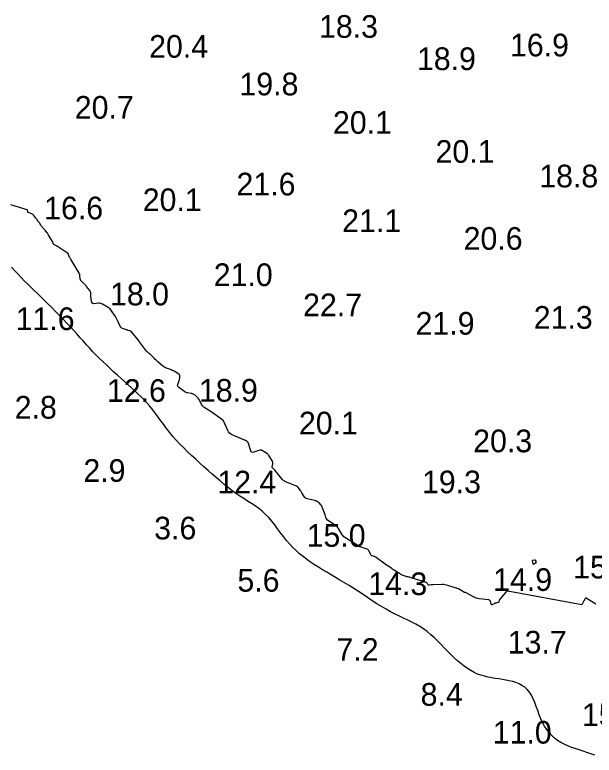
# Model space of a CAD drawing. Extents: x 3040093 to 3056816, y 408076 to 509144.
# Drawn here: x 3044162.7 to 3044290.6, y 435590.3 to 435753.7 of the extents above; entities that cross this region are included whole.
import ezdxf

# ---------------------------------------------------------------- set-up
doc = ezdxf.new("R2010")
doc.units = 0
for name, color, linetype in [('V-CHAN-CONT-EL12-1112', 7, 'Continuous'), ('V-CHAN-CONT-EL15', 7, 'Continuous'), ('V-TOPO-SOUN-0810', 7, 'Continuous')]:
    doc.layers.add(name, color=color, linetype=linetype)

msp = doc.modelspace()

# ---------------------------------------------------------------- linework, layer by layer
at = {"layer": 'V-CHAN-CONT-EL12-1112'}
msp.add_lwpolyline([(3044290.76, 435590.32), (3044289.9, 435590.65), (3044289.03, 435590.95), (3044288.16, 435591.23), (3044287.29, 435591.49), (3044286.43, 435591.77), (3044285.59, 435592.05), (3044284.77, 435592.37), (3044283.99, 435592.73), (3044283.24, 435593.13), (3044282.54, 435593.6), (3044281.88, 435594.11), (3044281.26, 435594.68), (3044280.68, 435595.3), (3044280.15, 435595.99), (3044279.67, 435596.72), (3044279.24, 435597.52), (3044278.85, 435598.37), (3044278.5, 435599.25), (3044278.16, 435600.16), (3044277.84, 435601.06), (3044277.51, 435601.93), (3044277.15, 435602.77), (3044276.77, 435603.54), (3044276.33, 435604.23), (3044275.83, 435604.81), (3044275.28, 435605.31), (3044274.68, 435605.72), (3044274.03, 435606.06), (3044273.34, 435606.34), (3044272.63, 435606.56), (3044271.89, 435606.74), (3044271.13, 435606.9), (3044270.36, 435607.03), (3044269.58, 435607.15), (3044268.79, 435607.27), (3044268.01, 435607.4), (3044267.22, 435607.55), (3044266.44, 435607.73), (3044265.66, 435607.96), (3044264.89, 435608.24), (3044264.13, 435608.59), (3044263.38, 435608.99), (3044262.64, 435609.45), (3044261.91, 435609.96), (3044261.19, 435610.53), (3044260.46, 435611.14), (3044259.74, 435611.79), (3044259.02, 435612.48), (3044258.3, 435613.21), (3044257.57, 435613.96), (3044256.84, 435614.72), (3044256.1, 435615.48), (3044255.34, 435616.22), (3044254.57, 435616.92), (3044253.78, 435617.59), (3044252.97, 435618.2), (3044252.13, 435618.75), (3044251.27, 435619.24), (3044250.39, 435619.7), (3044249.49, 435620.13), (3044248.56, 435620.56), (3044247.62, 435621), (3044246.66, 435621.46), (3044245.69, 435621.97), (3044244.69, 435622.52), (3044243.69, 435623.12), (3044242.67, 435623.76), (3044241.65, 435624.42), (3044240.62, 435625.1), (3044239.59, 435625.78), (3044238.56, 435626.46), (3044237.54, 435627.12), (3044236.52, 435627.76), (3044235.51, 435628.37), (3044234.51, 435628.97), (3044233.53, 435629.55), (3044232.56, 435630.12), (3044231.6, 435630.68), (3044230.67, 435631.24), (3044229.76, 435631.8), (3044228.87, 435632.37), (3044228.01, 435632.95), (3044227.17, 435633.54), (3044226.35, 435634.15), (3044225.57, 435634.79), (3044224.81, 435635.47), (3044224.07, 435636.18), (3044223.37, 435636.94), (3044222.69, 435637.74), (3044222.03, 435638.57), (3044221.39, 435639.43), (3044220.75, 435640.29), (3044220.1, 435641.14), (3044219.45, 435641.96), (3044218.77, 435642.75), (3044218.07, 435643.48), (3044217.33, 435644.15), (3044216.57, 435644.76), (3044215.77, 435645.34), (3044214.96, 435645.89), (3044214.12, 435646.42), (3044213.27, 435646.96), (3044212.41, 435647.52), (3044211.54, 435648.1), (3044210.67, 435648.73), (3044209.8, 435649.4), (3044208.92, 435650.1), (3044208.04, 435650.84), (3044207.16, 435651.6), (3044206.27, 435652.38), (3044205.38, 435653.18), (3044204.48, 435653.99), (3044203.57, 435654.8), (3044202.67, 435655.63), (3044201.77, 435656.46), (3044200.88, 435657.29), (3044200.02, 435658.13), (3044199.18, 435658.98), (3044198.38, 435659.83), (3044197.63, 435660.69), (3044196.92, 435661.55), (3044196.24, 435662.41), (3044195.6, 435663.27), (3044194.99, 435664.11), (3044194.38, 435664.95), (3044193.79, 435665.76), (3044193.19, 435666.55), (3044192.57, 435667.32), (3044191.94, 435668.05), (3044191.29, 435668.75), (3044190.61, 435669.43), (3044189.92, 435670.1), (3044189.21, 435670.77), (3044188.48, 435671.43), (3044187.73, 435672.09), (3044186.97, 435672.77), (3044186.19, 435673.46), (3044185.4, 435674.17), (3044184.6, 435674.89), (3044183.8, 435675.63), (3044183.01, 435676.37), (3044182.22, 435677.12), (3044181.45, 435677.87), (3044180.7, 435678.62), (3044179.98, 435679.38), (3044179.27, 435680.14), (3044178.57, 435680.9), (3044177.88, 435681.67), (3044177.18, 435682.44), (3044176.47, 435683.23), (3044175.74, 435684.04), (3044174.99, 435684.86), (3044174.2, 435685.7), (3044173.38, 435686.55), (3044172.55, 435687.41), (3044171.71, 435688.27), (3044170.87, 435689.11), (3044170.03, 435689.94), (3044169.21, 435690.75), (3044168.42, 435691.52), (3044167.66, 435692.26), (3044166.93, 435692.97), (3044166.21, 435693.66), (3044165.52, 435694.34), (3044164.83, 435695.03), (3044164.14, 435695.73), (3044163.44, 435696.45), (3044162.73, 435697.21), (3044162.01, 435698.01)], dxfattribs=at)
at = {"layer": 'V-CHAN-CONT-EL15'}
for points in [[(3044287.86, 435623.51), (3044271.91, 435626.42), (3044271.7, 435626.49), (3044271.5, 435626.49), (3044271.32, 435626.42), (3044271.15, 435626.27), (3044269.78, 435624.73), (3044269.73, 435624.67), (3044269.69, 435624.61), (3044269.66, 435624.54), (3044269.64, 435624.47), (3044269.56, 435624.18), (3044269.54, 435624.12), (3044269.5, 435624.06), (3044269.45, 435624.03), (3044269.38, 435624), (3044268.9, 435623.89), (3044268.8, 435623.86), (3044268.71, 435623.83), (3044268.61, 435623.79), (3044268.52, 435623.74), (3044268.15, 435623.55), (3044268.07, 435623.52), (3044268, 435623.53), (3044267.95, 435623.57), (3044267.91, 435623.65), (3044267.73, 435624.28), (3044267.68, 435624.41), (3044267.6, 435624.5), (3044267.49, 435624.56), (3044267.36, 435624.59), (3044265.25, 435624.86), (3044264.91, 435624.92), (3044264.59, 435625), (3044264.27, 435625.12), (3044263.96, 435625.27), (3044262.18, 435626.22), (3044262.17, 435626.23), (3044262.15, 435626.24), (3044262.14, 435626.24), (3044262.12, 435626.24), (3044262.06, 435626.23), (3044262.04, 435626.23), (3044262.03, 435626.23), (3044262.01, 435626.23), (3044262, 435626.24), (3044261.07, 435626.79), (3044261.03, 435626.82), (3044260.98, 435626.84), (3044260.94, 435626.86), (3044260.9, 435626.89), (3044260.66, 435627.02), (3044260.65, 435627.02), (3044260.64, 435627.02), (3044260.63, 435627.03), (3044260.62, 435627.03), (3044260.33, 435627.14), (3044260.28, 435627.16), (3044260.23, 435627.18), (3044260.18, 435627.19), (3044260.13, 435627.21), (3044258.33, 435627.79), (3044258.01, 435627.87), (3044257.69, 435627.94), (3044257.36, 435627.97), (3044257.03, 435627.98), (3044255.11, 435627.94), (3044255, 435627.94), (3044254.89, 435627.93), (3044254.78, 435627.93), (3044254.67, 435627.91), (3044254.18, 435627.86), (3044254.1, 435627.86), (3044254.04, 435627.88), (3044253.98, 435627.92), (3044253.93, 435627.98), (3044253.75, 435628.26), (3044253.71, 435628.33), (3044253.65, 435628.38), (3044253.58, 435628.43), (3044253.51, 435628.46), (3044250.01, 435629.56), (3044249.94, 435629.59), (3044249.87, 435629.61), (3044249.8, 435629.62), (3044249.72, 435629.64), (3044249.43, 435629.69), (3044249.36, 435629.71), (3044249.28, 435629.72), (3044249.21, 435629.75), (3044249.14, 435629.77), (3044248.26, 435630.09), (3044248.09, 435630.16), (3044247.93, 435630.23), (3044247.77, 435630.32), (3044247.62, 435630.41), (3044246.35, 435631.24), (3044246.22, 435631.32), (3044246.09, 435631.41), (3044245.97, 435631.49), (3044245.84, 435631.58), (3044245.19, 435632.02), (3044245.14, 435632.06), (3044245.08, 435632.1), (3044245.02, 435632.13), (3044244.96, 435632.17), (3044244.72, 435632.31), (3044244.67, 435632.35), (3044244.61, 435632.39), (3044244.55, 435632.42), (3044244.5, 435632.47), (3044242.49, 435633.95), (3044242.39, 435634.03), (3044242.28, 435634.09), (3044242.17, 435634.14), (3044242.05, 435634.19), (3044241.57, 435634.35), (3044241.46, 435634.4), (3044241.37, 435634.47), (3044241.29, 435634.56), (3044241.23, 435634.67), (3044240.94, 435635.38), (3044240.86, 435635.53), (3044240.76, 435635.65), (3044240.63, 435635.74), (3044240.48, 435635.81), (3044239.19, 435636.24), (3044239.16, 435636.25), (3044239.12, 435636.26), (3044239.08, 435636.27), (3044239.05, 435636.28), (3044238.83, 435636.33), (3044238.83, 435636.33), (3044238.83, 435636.34), (3044238.82, 435636.34), (3044238.81, 435636.35), (3044235.57, 435638.4), (3044235.38, 435638.54), (3044235.2, 435638.7), (3044235.05, 435638.88), (3044234.92, 435639.07), (3044234.25, 435640.21), (3044234.22, 435640.27), (3044234.18, 435640.33), (3044234.14, 435640.39), (3044234.1, 435640.45), (3044233.94, 435640.68), (3044233.9, 435640.74), (3044233.86, 435640.79), (3044233.8, 435640.84), (3044233.75, 435640.88), (3044231.87, 435642.09), (3044231.82, 435642.13), (3044231.77, 435642.18), (3044231.72, 435642.23), (3044231.68, 435642.28), (3044231.54, 435642.51), (3044231.51, 435642.57), (3044231.47, 435642.63), (3044231.45, 435642.7), (3044231.42, 435642.76), (3044231.22, 435643.34), (3044231.18, 435643.46), (3044231.14, 435643.57), (3044231.1, 435643.69), (3044231.06, 435643.81), (3044230.52, 435645.24), (3044230.48, 435645.34), (3044230.43, 435645.43), (3044230.37, 435645.52), (3044230.3, 435645.6), (3044229.98, 435645.92), (3044229.91, 435645.99), (3044229.84, 435646.05), (3044229.76, 435646.11), (3044229.68, 435646.16), (3044229.34, 435646.36), (3044229.25, 435646.4), (3044229.16, 435646.44), (3044229.07, 435646.47), (3044228.97, 435646.5), (3044227.25, 435646.91), (3044227.05, 435646.98), (3044226.88, 435647.08), (3044226.73, 435647.22), (3044226.61, 435647.39), (3044226.12, 435648.26), (3044226.04, 435648.39), (3044225.96, 435648.52), (3044225.88, 435648.64), (3044225.79, 435648.77), (3044225.28, 435649.42), (3044225.26, 435649.45), (3044225.23, 435649.48), (3044225.2, 435649.51), (3044225.17, 435649.54), (3044225.05, 435649.64), (3044225.01, 435649.67), (3044224.98, 435649.69), (3044224.95, 435649.71), (3044224.91, 435649.72), (3044222.34, 435650.72), (3044222.33, 435650.73), (3044222.32, 435650.74), (3044222.31, 435650.75), (3044222.3, 435650.76), (3044222.27, 435650.81), (3044222.26, 435650.82), (3044222.26, 435650.83), (3044222.25, 435650.84), (3044222.23, 435650.85), (3044221.93, 435651.04), (3044221.87, 435651.08), (3044221.82, 435651.12), (3044221.78, 435651.16), (3044221.73, 435651.21), (3044220.1, 435653.24), (3044220.04, 435653.3), (3044219.99, 435653.36), (3044219.93, 435653.42), (3044219.88, 435653.48), (3044219.64, 435653.71), (3044219.59, 435653.77), (3044219.56, 435653.83), (3044219.55, 435653.9), (3044219.55, 435653.98), (3044219.68, 435654.66), (3044219.69, 435654.8), (3044219.68, 435654.94), (3044219.64, 435655.06), (3044219.58, 435655.19), (3044218.84, 435656.45), (3044218.76, 435656.57), (3044218.67, 435656.68), (3044218.56, 435656.77), (3044218.45, 435656.86), (3044217.88, 435657.24), (3044217.79, 435657.29), (3044217.71, 435657.34), (3044217.62, 435657.39), (3044217.54, 435657.43), (3044217.18, 435657.61), (3044217.1, 435657.65), (3044217.01, 435657.66), (3044216.91, 435657.66), (3044216.82, 435657.64), (3044215.49, 435657.19), (3044215.26, 435657.14), (3044215.07, 435657.19), (3044214.92, 435657.31), (3044214.82, 435657.52), (3044214.23, 435659.3), (3044214.21, 435659.35), (3044214.18, 435659.4), (3044214.15, 435659.44), (3044214.11, 435659.48), (3044213.88, 435659.68), (3044213.86, 435659.69), (3044213.85, 435659.7), (3044213.83, 435659.71), (3044213.81, 435659.72), (3044213.73, 435659.74), (3044213.71, 435659.74), (3044213.69, 435659.75), (3044213.67, 435659.75), (3044213.65, 435659.76), (3044213.45, 435659.84), (3044213.41, 435659.86), (3044213.38, 435659.88), (3044213.34, 435659.89), (3044213.3, 435659.91), (3044210.74, 435661), (3044210.41, 435661.18), (3044210.13, 435661.4), (3044209.9, 435661.68), (3044209.72, 435662), (3044208.8, 435664.08), (3044208.8, 435664.1), (3044208.79, 435664.11), (3044208.79, 435664.12), (3044208.78, 435664.13), (3044208.76, 435664.17), (3044208.75, 435664.18), (3044208.74, 435664.19), (3044208.74, 435664.2), (3044208.73, 435664.2), (3044208.71, 435664.24), (3044208.7, 435664.25), (3044208.7, 435664.25), (3044208.69, 435664.26), (3044208.68, 435664.26), (3044208.65, 435664.26), (3044208.64, 435664.26), (3044208.63, 435664.26), (3044208.63, 435664.26), (3044208.62, 435664.27), (3044206.3, 435665.94), (3044206.1, 435666.07), (3044205.9, 435666.21), (3044205.69, 435666.34), (3044205.49, 435666.47), (3044204.66, 435666.96), (3044204.46, 435667.1), (3044204.29, 435667.26), (3044204.14, 435667.44), (3044204.01, 435667.64), (3044203.36, 435668.87), (3044203.31, 435668.96), (3044203.25, 435669.05), (3044203.19, 435669.13), (3044203.12, 435669.21), (3044202.83, 435669.51), (3044202.76, 435669.58), (3044202.68, 435669.65), (3044202.6, 435669.71), (3044202.51, 435669.76), (3044202.09, 435669.99), (3044201.99, 435670.04), (3044201.88, 435670.08), (3044201.78, 435670.12), (3044201.67, 435670.14), (3044200.87, 435670.27), (3044200.7, 435670.3), (3044200.55, 435670.36), (3044200.4, 435670.43), (3044200.25, 435670.52), (3044198.86, 435671.54), (3044198.72, 435671.67), (3044198.65, 435671.81), (3044198.64, 435671.97), (3044198.68, 435672.15), (3044199.02, 435673.02), (3044199.06, 435673.14), (3044199.1, 435673.26), (3044199.12, 435673.39), (3044199.13, 435673.51), (3044199.16, 435674.02), (3044199.16, 435674.14), (3044199.12, 435674.24), (3044199.06, 435674.33), (3044198.96, 435674.4), (3044197.89, 435675.05), (3044197.69, 435675.16), (3044197.49, 435675.26), (3044197.28, 435675.35), (3044197.07, 435675.44), (3044196.21, 435675.75), (3044196, 435675.83), (3044195.8, 435675.94), (3044195.61, 435676.06), (3044195.43, 435676.2), (3044194.3, 435677.16), (3044194.1, 435677.33), (3044193.92, 435677.5), (3044193.73, 435677.68), (3044193.55, 435677.85), (3044192.6, 435678.82), (3044192.54, 435678.88), (3044192.48, 435678.93), (3044192.41, 435678.99), (3044192.35, 435679.04), (3044192.07, 435679.25), (3044192.01, 435679.3), (3044191.94, 435679.36), (3044191.89, 435679.42), (3044191.83, 435679.49), (3044190.04, 435681.83), (3044190.04, 435681.84), (3044190.04, 435681.84), (3044190.04, 435681.84), (3044190.04, 435681.85), (3044190.04, 435681.86), (3044190.04, 435681.86), (3044190.04, 435681.87), (3044190.04, 435681.87), (3044190.03, 435681.87), (3044190.02, 435681.88), (3044190.01, 435681.88), (3044190.01, 435681.88), (3044190.01, 435681.89), (3044190, 435681.89), (3044188.46, 435683.78), (3044188.4, 435683.84), (3044188.32, 435683.9), (3044188.24, 435683.94), (3044188.15, 435683.97), (3044187.78, 435684.07), (3044187.69, 435684.09), (3044187.6, 435684.12), (3044187.51, 435684.14), (3044187.42, 435684.18), (3044186.49, 435684.5), (3044186.32, 435684.58), (3044186.18, 435684.69), (3044186.06, 435684.82), (3044185.97, 435684.99), (3044185.55, 435685.96), (3044185.5, 435686.07), (3044185.45, 435686.18), (3044185.4, 435686.29), (3044185.34, 435686.39), (3044185.12, 435686.82), (3044185.07, 435686.93), (3044185.01, 435687.03), (3044184.95, 435687.13), (3044184.88, 435687.23), (3044184.1, 435688.41), (3044183.93, 435688.63), (3044183.75, 435688.82), (3044183.54, 435689), (3044183.32, 435689.15), (3044182.09, 435689.87), (3044181.9, 435689.97), (3044181.7, 435690.03), (3044181.5, 435690.06), (3044181.28, 435690.06), (3044180.13, 435689.97), (3044180.06, 435689.97), (3044180, 435689.99), (3044179.94, 435690.03), (3044179.9, 435690.08), (3044179.73, 435690.34), (3044179.69, 435690.4), (3044179.66, 435690.47), (3044179.64, 435690.54), (3044179.63, 435690.61), (3044179.58, 435691), (3044179.56, 435691.09), (3044179.56, 435691.18), (3044179.55, 435691.27), (3044179.54, 435691.36), (3044179.51, 435692.24), (3044179.49, 435692.41), (3044179.44, 435692.57), (3044179.37, 435692.73), (3044179.28, 435692.87), (3044178.59, 435693.77), (3044178.47, 435693.92), (3044178.34, 435694.07), (3044178.21, 435694.21), (3044178.07, 435694.34), (3044177.42, 435694.94), (3044177.33, 435695.04), (3044177.26, 435695.15), (3044177.21, 435695.28), (3044177.18, 435695.41), (3044177.09, 435696.22), (3044177.08, 435696.24), (3044177.08, 435696.26), (3044177.08, 435696.28), (3044177.08, 435696.3), (3044177.07, 435696.38), (3044177.07, 435696.4), (3044177.07, 435696.42), (3044177.06, 435696.44), (3044177.05, 435696.46), (3044176.99, 435696.58), (3044176.97, 435696.61), (3044176.96, 435696.63), (3044176.95, 435696.66), (3044176.93, 435696.68), (3044175.16, 435699.66), (3044175.12, 435699.72), (3044175.09, 435699.78), (3044175.05, 435699.84), (3044175.01, 435699.9), (3044174.85, 435700.13), (3044174.81, 435700.19), (3044174.78, 435700.25), (3044174.75, 435700.32), (3044174.73, 435700.38), (3044174.6, 435700.84), (3044174.56, 435700.93), (3044174.51, 435701.01), (3044174.44, 435701.08), (3044174.36, 435701.14), (3044172.15, 435702.57), (3044172.06, 435702.63), (3044171.97, 435702.68), (3044171.88, 435702.73), (3044171.79, 435702.78), (3044171.37, 435703), (3044171.31, 435703.03), (3044171.27, 435703.08), (3044171.24, 435703.13), (3044171.22, 435703.19), (3044171.17, 435703.44), (3044171.16, 435703.51), (3044171.14, 435703.57), (3044171.11, 435703.63), (3044171.08, 435703.68), (3044170.07, 435705.27), (3044169.99, 435705.39), (3044169.92, 435705.5), (3044169.85, 435705.6), (3044169.77, 435705.71), (3044169.43, 435706.18), (3044169.36, 435706.26), (3044169.3, 435706.35), (3044169.23, 435706.43), (3044169.15, 435706.51), (3044168.85, 435706.82), (3044168.78, 435706.9), (3044168.71, 435706.98), (3044168.64, 435707.07), (3044168.58, 435707.15), (3044168.15, 435707.79), (3044168.09, 435707.88), (3044168.03, 435707.97), (3044167.96, 435708.06), (3044167.9, 435708.15), (3044167.65, 435708.51), (3044167.58, 435708.6), (3044167.52, 435708.69), (3044167.45, 435708.78), (3044167.38, 435708.87), (3044166.94, 435709.41), (3044166.84, 435709.52), (3044166.73, 435709.62), (3044166.6, 435709.7), (3044166.47, 435709.77), (3044165.7, 435710.09), (3044165.64, 435710.12), (3044165.6, 435710.16), (3044165.58, 435710.21), (3044165.57, 435710.28), (3044165.56, 435710.54), (3044165.55, 435710.6), (3044165.53, 435710.65), (3044165.49, 435710.69), (3044165.43, 435710.71), (3044161.84, 435711.76)], [(3044291.02, 435623.65), (3044288.85, 435624.95), (3044288.79, 435624.97), (3044288.74, 435624.97), (3044288.69, 435624.95), (3044288.65, 435624.89), (3044288.52, 435624.64), (3044288.48, 435624.57), (3044288.44, 435624.51), (3044288.41, 435624.44), (3044288.37, 435624.38), (3044287.86, 435623.51)]]:
    msp.add_lwpolyline(points, dxfattribs=at)
msp.add_lwpolyline([(3044277.74, 435633.12), (3044277.76, 435633.08), (3044277.76, 435633.04), (3044277.76, 435633), (3044277.76, 435632.82), (3044277.75, 435632.78), (3044277.73, 435632.74), (3044277.71, 435632.71), (3044277.68, 435632.69), (3044277.31, 435632.47), (3044277.24, 435632.44), (3044277.19, 435632.45), (3044277.15, 435632.48), (3044277.13, 435632.55), (3044276.99, 435633.17), (3044276.99, 435633.24), (3044277.01, 435633.29), (3044277.05, 435633.33), (3044277.11, 435633.35), (3044277.47, 435633.42), (3044277.52, 435633.42), (3044277.56, 435633.41), (3044277.59, 435633.39), (3044277.62, 435633.35), (3044277.72, 435633.16)], close=True, dxfattribs=at)

# ---------------------------------------------------------------- texts
at = {"layer": 'V-TOPO-SOUN-0810'}
for s, p in [('18.3 ', (3044229.88, 435748.65)), ('16.9 ', (3044272.04, 435744.55)), ('20.4 ', (3044192.38, 435744.25)), ('18.9 ', (3044251.5, 435741.53)), ('19.8 ', (3044212.32, 435735.95)), ('20.7 ', (3044175.97, 435730.8)), ('20.1 ', (3044232.96, 435727.46)), ('20.1 ', (3044255.6, 435721.06)), ('18.8 ', (3044278.5, 435715.64)), ('21.6 ', (3044211.67, 435713.87)), ('20.1 ', (3044190.97, 435710.4)), ('16.6 ', (3044169.21, 435708.59)), ('21.1 ', (3044234.99, 435705.77)), ('20.6 ', (3044261.8, 435701.87)), ('21.0 ', (3044206.65, 435693.86)), ('18.0 ', (3044183.75, 435689.6)), ('22.7 ', (3044226.37, 435687.2)), ('11.6 ', (3044162.91, 435684.15)), ('21.3 ', (3044277.28, 435684.44)), ('21.9 ', (3044251.2, 435683.13)), ('12.6 ', (3044183.06, 435668.3)), ('18.9 ', (3044203.37, 435668.34)), ('2.8', (3044162.71, 435664.6)), ('20.1 ', (3044225.45, 435661.12)), ('20.3 ', (3044263.91, 435657.18)), ('2.9', (3044177.87, 435650.65)), ('12.4 ', (3044207.44, 435648.09)), ('19.3 ', (3044252.61, 435648.13)), ('3.6', (3044193.5, 435637.95)), ('15.0 ', (3044227.15, 435636.31)), ('15.3 ', (3044285.98, 435629.33)), ('5.6', (3044211.87, 435626.41)), ('14.3 ', (3044240.75, 435625.65)), ('14.9 ', (3044268.32, 435626.58)), ('13.7 ', (3044271.54, 435612.76)), ('7.2', (3044233.74, 435611.15)), ('8.4', (3044252.31, 435601.24)), ('15.7 ', (3044287.91, 435596.75)), ('11.0 ', (3044268.23, 435592.88))]:
    msp.add_text(s, height=5, dxfattribs=at).set_placement(p)

doc.saveas('drawing.dxf')
